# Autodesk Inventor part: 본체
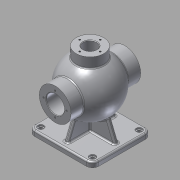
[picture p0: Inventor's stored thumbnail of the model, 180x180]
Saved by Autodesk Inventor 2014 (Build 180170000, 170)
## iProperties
Created: 2015-10
Part Number: 본체
Material: Aluminum 6061
Document SubType Name: Modeling
Designer: youjin19
Density: 2.71 g/cm^3
Appearance: Aluminum - Flat
Mass: 1524.24 g
Surface Area: 1156.04 cm^2
Volume: 562.449 cm^3
Author: youjin19
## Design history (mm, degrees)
sketch "Sketch1"
  geometry: L1 (57.5, 62.5)-(-57.5, 62.5); L2 (-57.5, 62.5)-(-57.5, -62.5); L3 (-57.5, -62.5)-(57.5, -62.5); L4 (57.5, -62.5)-(57.5, 62.5); L5 (57.5, 62.5)-(-57.5, -62.5); L6 (-57.5, 62.5)-(57.5, -62.5); 1 further point
  constraints: 12 end point, 2 midpoint, 2 parallel, 1 horizontal, 1 perpendicular
  dimensions: "d0" = 115 distance of L3.end L2.end; "d1" = 125 distance of L2.end L1.end
extrude "Extrusion1" new body sketch "Sketch1" distance "d2" = 10; taper "d3" = 0 deg
sketch "Sketch10"
  geometry: L1 (-68, 116)-(68, 116); L2 (68, 116)-(68, 85); L3 (68, 85)-(-68, 85); L4 (-68, 85)-(-68, 116); L5 (-57.5, 0)-(57.5, 0) reference; A1 r 53 centre (0, 85) between (53, 85) and (-53, 85); A2 r 53 centre (0, 85) between (-53, 85) and (53, 85); 3 further points
  constraints: 8 end point, 4 point on circle, 2 centre point, 2 midpoint, 2 parallel, 2 point on line, 1 coincident, 1 horizontal, 1 perpendicular, 1 vertical alignment
  dimensions: "d37" = 136 distance between parallel lines of L2 L4; "d38" = 62 diameter of L1 L3; "d39" = 85 distance from line of point (0, 85) L5; "d40" = 106 diameter of A1
revolve "Revolution3" sketch "Sketch10" stored, may be unused: angle "d41" = 90 deg
sketch "Sketch11"
  geometry: L1 (-57.5, -62.5)-(57.5, -62.5) reference; L2 (57.5, -62.5)-(57.5, 62.5) reference; L3 (-4, -52.5)-(4, -52.5); L4 (4, -52.5)-(4, 52.5); L5 (4, 52.5)-(-4, 52.5); L6 (-4, 52.5)-(-4, -52.5); L7 (-4, -52.5)-(4, 52.5); L8 (4, -52.5)-(-4, 52.5); L9 (-47.5, 4)-(47.5, 4); L10 (47.5, 4)-(47.5, -4); L11 (47.5, -4)-(-47.5, -4); L12 (-47.5, -4)-(-47.5, 4); L13 (-47.5, 4)-(47.5, -4); L14 (47.5, 4)-(-47.5, -4); 1 further point
  constraints: 24 end point, 4 midpoint, 4 parallel, 2 horizontal, 2 perpendicular
  dimensions: "d42" = 8 distance between parallel lines of L9 L11; "d43" = 8 distance between parallel lines of L6 L4; "d44" = 10 distance between parallel lines of L2 L10; "d45" = 10 distance between parallel lines of L1 L3
extrude "Extrusion7" join sketch "Sketch11" stored distance "d46" = 10; taper "d47" = 0 deg
feature "FaceDraft5" dims angle "d48" = 22 deg
feature "FaceDraft6" dims angle "d49" = 22 deg
feature "FaceDraft7" dims angle "d50" = 22 deg
feature "FaceDraft8" dims angle "d51" = 22 deg
sketch "Sketch12"
  geometry: L1 (-68, 54)-(-68, 116) reference; L2 (57.5, 0)-(-57.5, 0) reference; L3 (0, 85)-(-43, 85); L4 (0, 85)-(43, 85); A1 r 43 centre (0, 85) between (43, 85) and (-43, 85); A2 r 43 centre (0, 85) between (-43, 85) and (43, 85); 2 further points
  constraints: 4 end point, 4 point on circle, 2 centre point, 1 collinear, 1 horizontal alignment, 1 midpoint, 1 parallel, 1 vertical alignment
  dimensions: "d52" = 86 diameter of A1; "d53" = 85 distance from line of L3.start L2 (derived)
revolve "Revolution4" sketch "Sketch12" stored, may be unused: angle "d55" = 90 deg
sketch "Sketch13"
  geometry: C1 r 31 at (0, 0) reference; C2 r 17.5 at (0, 0); 1 further point
  constraints: 1 centre point, 1 coincident
  dimensions: "d56" = 35 diameter of C2
extrude "Extrusion8" cut sketch "Sketch13" stored distance "d57" = 10; taper "d58" = 0 deg
sketch "Sketch14"
  geometry: C1 r 31 at (0, 0) reference; C2 r 17.5 at (0, 0); 1 further point
  constraints: 1 centre point, 1 coincident
  dimensions: "d59" = 35 diameter of C2
extrude "Extrusion9" cut sketch "Sketch14" distance "d60" = 16; taper "d61" = 0 deg
sketch "Sketch15"
  geometry: C1 r 17.5 at (0, 0) reference; C2 r 18.5 at (0, 0); 1 further point
  constraints: 1 centre point, 1 coincident
  dimensions: "d62" = 37 diameter of C2
extrude "Extrusion10" cut sketch "Sketch15" distance "d63" = 1.75; taper "d64" = 0 deg
sketch "Sketch16"
  geometry: C1 r 18.5 at (0, 0) reference; C2 r 17.5 at (0, 0); 1 further point
  constraints: 1 centre point, 1 coincident
  dimensions: "d65" = 35 diameter of C2
extrude "Extrusion11" cut sketch "Sketch16" stored distance "d66" = 1.75; taper "d67" = 0 deg
fillet "Fillet1" dims "d68" = 12
sketch "Sketch17"
  geometry: L1 (45.5, 62.5)-(-45.5, 62.5) reference; L2 (-57.5, 50.5)-(-57.5, -50.5) reference; L3 (-45.5, -62.5)-(45.5, -62.5) reference; L4 (57.5, -50.5)-(57.5, 50.5) reference; L5 (4, -4)-(4, -52.5) reference; L6 (4, -52.5)-(-4, -52.5) reference; L7 (-4, -52.5)-(-4, -4) reference; L8 (-4, -4)-(-47.5, -4) reference; L9 (-47.5, -4)-(-47.5, 4) reference; L10 (-47.5, 4)-(-4, 4) reference; L11 (-4, 4)-(-4, 52.5) reference; L12 (-4, 52.5)-(4, 52.5) reference; L13 (4, 52.5)-(4, 4) reference; L14 (4, 4)-(47.5, 4) reference; L15 (47.5, 4)-(47.5, -4) reference; L16 (47.5, -4)-(4, -4) reference; A1 r 12 centre (45.5, 50.5) between (57.5, 50.5) and (45.5, 62.5) reference; A2 r 12 centre (-45.5, 50.5) between (-45.5, 62.5) and (-57.5, 50.5) reference; A3 r 12 centre (-45.5, -50.5) between (-57.5, -50.5) and (-45.5, -62.5) reference; A4 r 12 centre (45.5, -50.5) between (45.5, -62.5) and (57.5, -50.5) reference; 1 further point
hole "Hole2" diameter "d80" = 8; stored, may be unused: countersink angle "d84" = 90 deg, drill point angle "d86" = 0 deg; dims "d78" = 10, "d79" = 10, "d81" = 6, "d82" = 12, "d83" = 3, "d85" = 10
hole "Hole3" diameter "d89" = 8; stored, may be unused: countersink angle "d93" = 90 deg, drill point angle "d95" = 0 deg; dims "d87" = 10, "d88" = 10, "d90" = 6, "d91" = 12, "d92" = 3, "d94" = 10
hole "Hole4" diameter "d98" = 8; stored, may be unused: countersink angle "d102" = 90 deg, drill point angle "d104" = 0 deg; dims "d96" = 10, "d97" = 10, "d99" = 6, "d100" = 12, "d101" = 3, "d103" = 10
hole "Hole5" diameter "d107" = 8; stored, may be unused: countersink angle "d111" = 90 deg, drill point angle "d113" = 0 deg; dims "d105" = 10, "d106" = 10, "d108" = 6, "d109" = 12, "d110" = 3, "d112" = 10
workplane "Work Plane1"
sketch "Sketch18"
  geometry: C1 r 27 at (0, 0); 1 further point
  constraints: 1 centre point, 1 coincident
  dimensions: "d115" = 54 diameter of C1
extrude "Extrusion12" join sketch "Sketch18" stored distance "d116" = 1.75; taper "d117" = 0 deg; dims "d52" = 86
sketch "Sketch19"
  geometry: C1 r 27 at (0, 0) reference; C2 r 13 at (0, 0)
  constraints: 1 centre point, 1 coincident
  dimensions: "d118" = 26 diameter of C2
extrude "Extrusion13" cut sketch "Sketch19" distance "d119" = 50; taper "d120" = 0 deg
sketch "Sketch20"
  geometry: C1 r 17.5 at (0, 0) reference; C2 r 31 at (0, 0) reference; A1 r 22.5 centre (0, 0) between (0, 22.5) and (22.5, 0); 3 further points
  constraints: 4 point on circle, 2 horizontal alignment, 2 vertical alignment, 1 centre point, 1 coincident
  dimensions: "d121" = 45 diameter of A1
hole "Hole6" sketch "Sketch20" at (0, 22.5), (22.5, 0), (0, -22.5), (-22.5, 0) diameter "d122" = 3.242; stored, may be unused: countersink angle "d126" = 90 deg, drill point angle "d128" = 118 deg; dims "d123" = 12, "d124" = 12, "d125" = 3, "d127" = 15
sketch "Sketch21"
  geometry: C1 r 17.5 at (0, 0) reference; C2 r 31 at (0, 0) reference; A1 r 24 centre (0, 0) between (0, 24) and (24, 0); 3 further points
  constraints: 4 point on circle, 2 horizontal alignment, 2 vertical alignment, 1 centre point, 1 coincident
  dimensions: "d129" = 48 diameter of A1
hole "Hole7" sketch "Sketch21" at (0, 24), (24, 0), (0, -24), (-24, 0) diameter "d130" = 3.242; stored, may be unused: countersink angle "d134" = 90 deg, drill point angle "d136" = 118 deg; dims "d131" = 16, "d132" = 12, "d133" = 3, "d135" = 19
sketch "Sketch22"
  geometry: C1 r 13 at (0, 0) reference; C2 r 27 at (0, 0) reference; A1 r 20 centre (0, 0) between (0, 20) and (0, -20); 2 further points
  constraints: 4 point on circle, 2 horizontal alignment, 2 vertical alignment, 1 centre point, 1 coincident
  dimensions: "d137" = 40 diameter of A1
hole "Hole8" sketch "Sketch22" at (0, 20), (20, 0), (0, -20), (-20, 0) diameter "d138" = 3.242; stored, may be unused: countersink angle "d142" = 90 deg, drill point angle "d144" = 118 deg; dims "d139" = 9, "d140" = 12, "d141" = 3, "d143" = 11
workplane "Work Plane2"
sketch "Sketch23"
  geometry: L1 (-45.5, -150)-(45.5, -150) reference; L2 (-27, 0)-(-27, -19.393) reference; L3 (-27, 0)-(27, 0) reference; L4 (-27, 0)-(-27, -19.393) reference; L5 (-27, 0)-(27, 0) reference; L6 (-27, -19.393)-(27, -19.393) reference; 3 further points
  constraints: 1 midpoint, 1 vertical alignment, 1 other
  dimensions: "d145" = 27 distance from line of point (0, -10) L2 (derived); "d146" = 10 distance from line of point (0, -10) L3
emboss "Emboss1" sketch "Sketch23" dims "d147" = 0.5, "d148" = 0
fillet "Fillet2" dims "d149" = 3
fillet "Fillet3" dims "d150" = 3
fillet "Fillet4" dims "d151" = 3
fillet "Fillet5" dims "d152" = 3
fillet "Fillet6" dims "d153" = 3
fillet "Fillet7" dims "d154" = 3
chamfer "Chamfer1" distance "d155" = 1; stored, may be unused: second distance "d156" = 2, angle "d157" = 45 deg
body "Solid1"
node "Projected Loop1"
